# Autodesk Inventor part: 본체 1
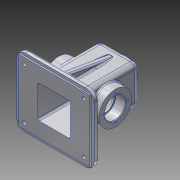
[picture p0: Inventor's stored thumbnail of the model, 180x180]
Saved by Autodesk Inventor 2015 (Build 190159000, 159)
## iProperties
Created: 2016-02
Part Number: 본체 1
Material: 알루미늄 6061
Document SubType Name: Modeling
Designer: Administrator
Density: 2.7 g/cm^3
Appearance: 알루미늄 - 평지
Author: Administrator
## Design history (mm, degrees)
sketch "스케치1"
  geometry: L1 (-65, 57.5)-(65, 57.5); L2 (65, 57.5)-(65, -57.5); L3 (65, -57.5)-(-65, -57.5); L4 (-65, -57.5)-(-65, 57.5); L5 (-65, 57.5)-(65, -57.5); L6 (65, 57.5)-(-65, -57.5); 1 further point
  constraints: 12 end point, 2 midpoint, 2 parallel, 1 horizontal, 1 perpendicular
  dimensions: "d0" = 115 distance of L1.end L2.end; "d1" = 130 distance of L1.start L1.end
extrude "돌출1" new body sketch "스케치1" distance "d2" = 8; taper "d3" = 0 deg
sketch "스케치2"
  geometry: L1 (-60, -52.5)-(60, -52.5); L2 (60, -52.5)-(60, 52.5); L3 (60, 52.5)-(-60, 52.5); L4 (-60, 52.5)-(-60, -52.5); L5 (-60, -52.5)-(60, 52.5); L6 (60, -52.5)-(-60, 52.5); 1 further point
  constraints: 12 end point, 2 midpoint, 2 parallel, 1 horizontal, 1 perpendicular
  dimensions: "d4" = 120 distance of L2.end L3.end; "d5" = 105 distance of L1.end L2.end
extrude "돌출2" join sketch "스케치2" distance "d6" = 2; taper "d7" = 0 deg
sketch "스케치3"
  geometry: L1 (32.5, 32.5)-(-32.5, 32.5); L2 (-32.5, 32.5)-(-32.5, -32.5); L3 (-32.5, -32.5)-(32.5, -32.5); L4 (32.5, -32.5)-(32.5, 32.5); L5 (32.5, 32.5)-(-32.5, -32.5); L6 (-32.5, 32.5)-(32.5, -32.5); 1 further point
  constraints: 12 end point, 2 midpoint, 2 parallel, 1 horizontal, 1 perpendicular
  dimensions: "d8" = 65 distance of L2.end L3.end; "d9" = 65 distance of L1.end L2.end
extrude "돌출3" join sketch "스케치3" distance "d10" = 100; taper "d11" = 0 deg
node "작업 평면1"
sketch "스케치4"
  geometry: L1 (-2, -52.5)-(-2, 52.5) reference; C1 r 27.5 at (53, 0); 1 further point
  constraints: 1 centre point, 1 horizontal alignment
  dimensions: "d13" = 55 diameter of C1; "d14" = 55 distance from line of L1 C1.centre
extrude "돌출4" join sketch "스케치4" stored distance "d15" = 100; taper "d16" = 0 deg
node "작업 평면2"
sketch "스케치5"
  geometry: C1 r 20 at (0, 0); 1 further point
  constraints: 1 centre point, 1 coincident
  dimensions: "d18" = 40 diameter of C1
extrude "돌출5" join sketch "스케치5" stored distance "d19" = 100; taper "d20" = 0 deg
hole "구멍1" diameter "d23" = 35; stored, may be unused: countersink angle "d27" = 90 deg, drill point angle "d29" = 0 deg; dims "d21" = 10, "d22" = 10, "d24" = 6, "d25" = 4, "d26" = 2, "d28" = 17
hole "구멍2" diameter "d32" = 30; stored, may be unused: countersink angle "d36" = 90 deg, drill point angle "d38" = 0 deg; dims "d30" = 10, "d31" = 10, "d33" = 6, "d34" = 4, "d35" = 2, "d37" = 3
sketch "스케치6"
  geometry: L1 (27.5, -27.5)-(-27.5, -27.5); L2 (-27.5, -27.5)-(-27.5, 27.5); L3 (-27.5, 27.5)-(27.5, 27.5); L4 (27.5, 27.5)-(27.5, -27.5); L5 (27.5, -27.5)-(-27.5, 27.5); L6 (-27.5, -27.5)-(27.5, 27.5); 1 further point
  constraints: 12 end point, 2 midpoint, 2 parallel, 1 horizontal, 1 perpendicular
  dimensions: "d39" = 55 distance of L1.end L2.end; "d40" = 55 distance of L2.end L3.end
extrude "돌출6" cut sketch "스케치6" distance "d41" = 105; taper "d42" = 0 deg
hole "구멍3" diameter "d45" = 21; stored, may be unused: countersink angle "d49" = 90 deg, drill point angle "d51" = 0 deg; dims "d43" = 10, "d44" = 10, "d46" = 6, "d47" = 4, "d48" = 2, "d50" = 20
sketch "스케치7" dims "d53" = 42
  geometry: L1 (-52.5, -55)-(52.5, -55) reference; C1 r 2 at (0, 21); C2 r 2 at (-21, 0); C3 r 2 at (0, -21); C4 r 2 at (21, 0); 2 further points
  constraints: 4 centre point, 2 vertical alignment, 11 other
  dimensions: "d54" = 55 distance from line of L1 point (0, 0); "d55" = 4 diameter of C1; "d57" = 76 distance from line of L1 C1.centre; "d60" = 360 deg dimension on point (0, 0) C1.centre (derived)
hole "구멍4" sketch "스케치7" at (0, 21), (-21, 0), (0, -21), (21, 0) diameter "d62" = 3.242; stored, may be unused: countersink angle "d66" = 90 deg, drill point angle "d68" = 118 deg; dims "d63" = 8, "d64" = 4, "d65" = 2, "d67" = 10
sketch "스케치8" dims "d69" = 29
  geometry: C1 r 1.5 at (0, 14.5); C2 r 1.5 at (-14.5, 0); C3 r 1.5 at (0, -14.5); C4 r 1.5 at (14.5, 0); 2 further points
  constraints: 4 centre point, 2 vertical alignment, 1 coincident, 11 other
  dimensions: "d70" = 3 diameter of C1; "d73" = 360 deg dimension on point (0, 0) C1.centre (derived)
hole "구멍5" sketch "스케치8" at (0, -14.5), (-14.5, 0), (14.5, 0), (0, 14.5) diameter "d75" = 2.459; stored, may be unused: countersink angle "d79" = 90 deg, drill point angle "d81" = 118 deg; dims "d76" = 7, "d77" = 4, "d78" = 2, "d80" = 9
sketch "스케치9"
  geometry: L1 (-60, 52.5)-(-60, -52.5) reference; L2 (-60, -52.5)-(60, -52.5) reference; L3 (60, -52.5)-(60, 52.5) reference; L4 (60, 52.5)-(-60, 52.5) reference; L5 (65, -57.5)-(-65, -57.5) reference; L6 (-65, -57.5)-(-65, 57.5) reference; L7 (-65, 57.5)-(65, 57.5) reference; L8 (65, 57.5)-(65, -57.5) reference; L9 (0, 0)-(0, -66.144); L10 (0, 0)-(-52.298, 0); C1 r 7.5 at (-50, -42.5); C2 r 7.5 at (-50, 42.5); C3 r 7.5 at (50, -42.5); C4 r 7.5 at (50, 42.5)
  constraints: 4 centre point, 4 end point, 3 symmetric about line, 1 horizontal, 1 vertical, 3 other
  dimensions: "d82" = 15 diameter of C1; "d83" = 15 distance from line of C1.centre L6; "d84" = 15 distance from line of L5 C1.centre
extrude "돌출7" join sketch "스케치9" distance "d85" = 3; taper "d86" = 0 deg
sketch "스케치10"
  geometry: L1 (50, 42.5)-(-7.031, 42.5); L2 (50, 42.5)-(50, -23.271); C1 r 7.5 at (0, 0) reference; C2 r 3 at (0, 0); C3 r 3 at (0, 85); C4 r 3 at (100, 0); C5 r 3 at (100, 85)
  constraints: 4 centre point, 4 end point, 3 symmetric about line, 1 coincident, 1 horizontal, 1 vertical, 3 other
  dimensions: "d88" = 6 diameter of C2
hole "구멍6" sketch "스케치10" at (0, 0), (100, 0), (100, 85), (0, 85) diameter "d89" = 6; stored, may be unused: countersink angle "d93" = 90 deg, drill point angle "d95" = 0 deg; dims "d90" = 7, "d91" = 4, "d92" = 2, "d94" = 9
sketch "스케치12"
  geometry: L1 (8, 32.5)-(108, 32.5) reference; L2 (8, -57.5)-(8, 57.5) reference; L3 (8, 47.5)-(93.069, 32.5); L4 (8, 32.5)-(8, 47.5); L5 (93.069, 32.5)-(8, 32.5); L6 (0, 57.5)-(8, 57.5) reference; 1 further point
  constraints: 6 end point, 2 point on line, 1 collinear, 1 perpendicular
  dimensions: "d98" = 10 deg angle of L3 L6; "d99" = 10 distance from line of L6 L3.start
extrude "돌출8" join sketch "스케치12" stored distance "d100" = 10; taper "d101" = 0 deg
sketch "스케치13"
  geometry: L1 (32.5, 8)-(32.5, 108) reference; L2 (32.5, 8)-(42.5, 8); L3 (42.5, 8)-(42.5, 28); L4 (42.5, 28)-(32.5, 28); L5 (32.5, 28)-(32.5, 8); L6 (27.5, -2)-(27.5, 103) reference; 1 further point
  constraints: 8 end point, 2 parallel, 1 horizontal, 1 perpendicular, 1 point on line
  dimensions: "d102" = 15 distance between parallel lines of L3 L6; "d117" = 20 distance of L2.end L3.end
extrude "돌출9" join sketch "스케치13" stored distance "d103" = 6; taper "d104" = 0 deg
chamfer "모따기1" distance "d105" = 1; stored, may be unused: second distance "d106" = 2, angle "d107" = 45 deg
chamfer "모따기2" distance "d108" = 1; stored, may be unused: second distance "d109" = 2, angle "d110" = 45 deg
fillet "모깎기1" dims "d111" = 15
fillet "모깎기2" dims "d112" = 15
fillet "모깎기3" dims "d113" = 15
fillet "모깎기4" dims "d114" = 15
fillet "모깎기5" dims "d115" = 2.5
fillet "모깎기6" dims "d116" = 2.5
fillet "모깎기7"
fillet "모깎기8"
fillet "모깎기9" dims "d118" = 3
fillet "모깎기10" dims "d119" = 3
fillet "모깎기11" dims "d120" = 3
fillet "모깎기12" dims "d121" = 3
feature "면 기울기1" dims angle "d122" = 5 deg
fillet "모깎기13" dims "d123" = 8
fillet "모깎기14" dims "d124" = 8
fillet "모깎기15" dims "d125" = 3
fillet "모깎기16" dims "d126" = 3
fillet "모깎기17" dims "d127" = 3
fillet "모깎기19" dims "d129" = 3
fillet "모깎기20" dims "d130" = 3
fillet "모깎기21" dims "d131" = 3
fillet "모깎기22" dims "d132" = 3
fillet "모깎기23" dims "d133" = 1
fillet "모깎기24" dims "d134" = 3
fillet "모깎기25" dims "d135" = 0.3
fillet "모깎기26" dims "d136" = 3
sketch "스케치14"
  geometry: L1 (-8, 0)-(-8, -91) reference; L2 (77, -102)-(-28, -102) reference; L3 (5.375, 18)-(43.625, 18) reference; C1 r 15 at (24.5, -47) reference; 2 further points
  constraints: 1 other
  dimensions: "d137" = 32.5 distance from line of L1 point (24.5, -8); "d139" = 26 distance from line of point (24.5, -8) L3
feature "엠보싱1" sketch "스케치14" dims "d140" = 0.5, "d141" = 0
node "솔리드1"
mirror "대칭1"
mirror "대칭2"
mirror "대칭3"
mirror "대칭4"
mirror "대칭5"
mirror "대칭6"
node "투영된 루프1"
other parameters: "d12" = -47.5, "d17" = 118
